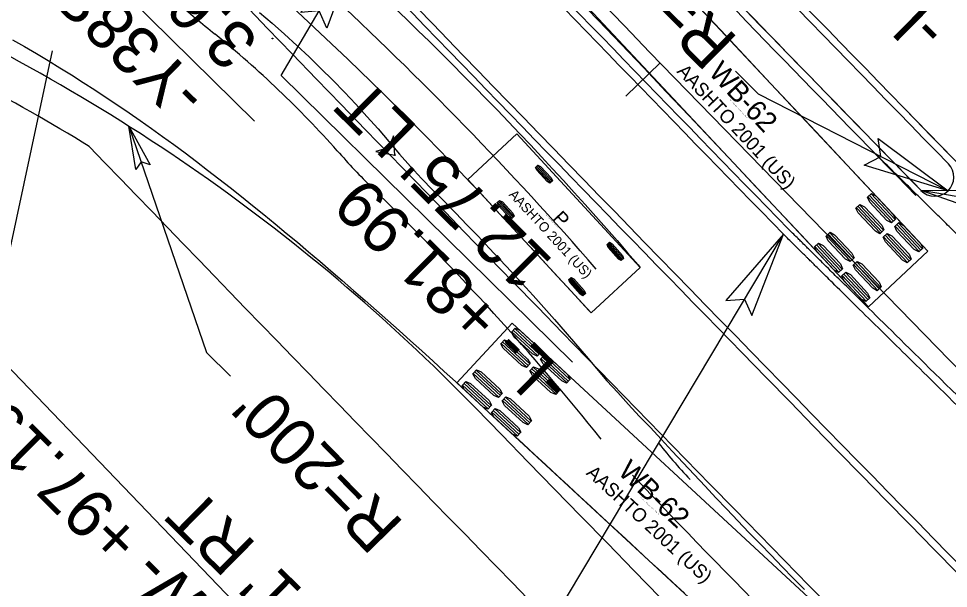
# Model space of a CAD drawing. Extents: x 1262642 to 1268358, y 767825 to 773481.
# Drawn here: x 1266795.4 to 1266892.6, y 772031 to 772090.6 of the extents above; entities that cross this region are included whole.
import ezdxf

# ---------------------------------------------------------------- set-up
doc = ezdxf.new("R2010")
doc.units = 0
for name, color, linetype in [('Prop Conc 1ft 6in Curb and Gutter', 7, 'Continuous'), ('Prop Conc 5in Monolithic Keyed In Island', 7, 'Continuous'), ('Prop Dimension', 7, 'Continuous'), ('Prop Dimension Text', 7, 'Continuous'), ('Prop EOT', 7, 'Continuous'), ('Prop Horizontal Alignment', 7, 'Continuous'), ('Prop Horizontal Alignment Tick Small', 7, 'Continuous'), ('Prop Lane Lines', 7, 'Continuous'), ('Prop Paved Shoulder', 7, 'Continuous'), ('Prop Shade Light', 7, 'Continuous'), ('Prop Shade Medium', 7, 'Continuous'), ('Prop Terminator CELL', 7, 'Continuous'), ('Scratch_Level_3', 7, 'Continuous')]:
    doc.layers.add(name, color=color, linetype=linetype)

msp = doc.modelspace()

# ---------------------------------------------------------------- linework, layer by layer
at = {"layer": 'Prop Conc 1ft 6in Curb and Gutter'}
msp.add_arc((1275047.307, 780021.225), 11414.25, 223.9578669, 225.4193188, dxfattribs=at)
msp.add_open_spline([(1266926.159, 772018.122), (1266925.893, 772018.382), (1266925.627, 772018.641), (1266925.229, 772019.03), (1266925.096, 772019.16), (1266924.897, 772019.354), (1266924.831, 772019.419), (1266924.698, 772019.549), (1266924.632, 772019.613), (1266924.034, 772020.197), (1266923.503, 772020.716), (1266921.91, 772022.273), (1266920.848, 772023.311), (1266917.663, 772026.425), (1266911.295, 772032.657), (1266900.694, 772043.056), (1266892.226, 772051.388), (1266885.88, 772057.643), (1266883.766, 772059.728), (1266880.595, 772062.858), (1266879.539, 772063.901), (1266878.35, 772065.075), (1266878.218, 772065.206), (1266878.02, 772065.401), (1266877.954, 772065.467), (1266877.822, 772065.597), (1266877.756, 772065.663), (1266877.425, 772065.989), (1266877.161, 772066.25), (1266876.633, 772066.771), (1266876.37, 772067.032), (1266875.842, 772067.554), (1266875.578, 772067.814), (1266875.315, 772068.075)], degree=3, dxfattribs=at)
at = {"layer": 'Prop Conc 5in Monolithic Keyed In Island'}
for centre, radius, start, end in [((1275047.307, 780021.225), 11385.75, 223.6505027, 224.2564693), ((1275047.307, 780021.225), 11389.75, 223.8019285, 224.2564698), ((1275047.307, 780021.225), 11389.75, 223.87202, 224.2564698), ((1275047.307, 780021.225), 11403.25, 223.9579874, 224.2224607), ((1266891.136, 772074.041), 2, 314.25374, 44.25374), ((1266891.136, 772074.041), 2, 224.25374, 314.25374)]:
    msp.add_arc(centre, radius, start, end, dxfattribs=at)
at = {"layer": 'Prop Dimension'}
msp.add_line((1266806.891, 772079.366), (1266814.985, 772055.706), dxfattribs=at)
at = {"layer": 'Prop Dimension Text'}
for p, q in [((1266820.023, 772079.893), (1266772.475, 772126.743)), ((1266822.822, 772084.668), (1266853.266, 772054.672)), ((1266872.691, 772082.773), (1266870.307, 772085.122)), ((1266872.691, 772082.773), (1266892.54, 772072.599)), ((1266832.757, 772014.086), (1266791.444, 772057.149)), ((1266814.985, 772055.706), (1266817.513, 772053.215))]:
    msp.add_line(p, q, dxfattribs=at)
for points in [[(1266822.822, 772084.668), (1266830.753, 772098.262)], [(1266792.936, 772059.488), (1266798.897, 772087.243)], [(1266907.856, 772069.557), (1266889.705, 772072.645)], [(1266843.752, 772015.175), (1266875.312, 772068.074)]]:
    msp.add_lwpolyline(points, dxfattribs=at)
at = {"layer": 'Prop EOT'}
for centre, radius, start, end in [((1275047.307, 780021.225), 11385, 223.6505027, 224.2564693), ((1275047.307, 780021.225), 11349, 223.9768445, 225.4019123), ((1275047.307, 780021.225), 11390.5, 223.8019285, 224.2564693), ((1275047.307, 780021.225), 11402.5, 223.9578586, 224.2223874), ((1275047.307, 780021.225), 11415, 223.9578709, 224.2520264), ((1266699.67, 771910.536), 200, 44.17518, 66.65746), ((1275047.307, 780021.225), 11415, 224.2520264, 225.4043192), ((1275047.307, 780021.225), 11439, 224.1751818, 225.4433837)]:
    msp.add_arc(centre, radius, start, end, dxfattribs=at)
msp.add_open_spline([(1266926.683, 772018.659), (1266926.417, 772018.918), (1266926.019, 772019.308), (1266925.62, 772019.696), (1266925.421, 772019.891), (1266925.355, 772019.955), (1266925.222, 772020.085), (1266924.625, 772020.669), (1266922.965, 772022.29), (1266919.249, 772025.923), (1266911.82, 772033.193), (1266901.22, 772043.591), (1266890.635, 772054.006), (1266883.235, 772061.305), (1266879.933, 772064.565), (1266878.745, 772065.739), (1266878.547, 772065.935), (1266878.481, 772066), (1266878.349, 772066.131), (1266878.018, 772066.457), (1266877.688, 772066.783), (1266877.161, 772067.305), (1266876.897, 772067.566), (1266876.369, 772068.087), (1266876.106, 772068.348), (1266875.842, 772068.608)], degree=3, dxfattribs=at)
at = {"layer": 'Prop Horizontal Alignment'}
msp.add_arc((1275047.307, 780021.225), 11400, 222.9935866, 225.4043192, dxfattribs=at)
at = {"layer": 'Prop Horizontal Alignment Tick Small'}
msp.add_line((1266862.433, 772085.997), (1266858.844, 772082.516), dxfattribs=at)
at = {"layer": 'Prop Lane Lines'}
for radius, start, end in [(11427, 222.9935866, 225.3637298), (11373, 223.9768445, 224.2564693), (11385, 224.2212142, 225.4043192)]:
    msp.add_arc((1275047.307, 780021.225), radius, start, end, dxfattribs=at)
msp.add_spline([(1266935.066, 772027.245), (1266934.378, 772027.917), (1266933.689, 772028.589), (1266933.001, 772029.262), (1266932.313, 772029.934), (1266931.625, 772030.606), (1266930.937, 772031.279), (1266930.249, 772031.951), (1266929.561, 772032.624), (1266928.873, 772033.296), (1266928.185, 772033.969), (1266927.497, 772034.642), (1266926.809, 772035.315), (1266926.122, 772035.987), (1266925.434, 772036.66), (1266924.746, 772037.333), (1266924.059, 772038.006), (1266923.371, 772038.679), (1266922.684, 772039.353), (1266921.997, 772040.026), (1266921.309, 772040.699), (1266920.622, 772041.372), (1266919.935, 772042.046), (1266919.248, 772042.719), (1266918.561, 772043.393), (1266917.874, 772044.066), (1266917.187, 772044.74), (1266916.5, 772045.414), (1266915.813, 772046.087), (1266915.126, 772046.761), (1266914.439, 772047.435), (1266913.752, 772048.109), (1266913.066, 772048.783), (1266912.379, 772049.457), (1266911.693, 772050.131), (1266911.006, 772050.805), (1266910.32, 772051.479), (1266909.633, 772052.154), (1266908.947, 772052.828), (1266908.261, 772053.502), (1266907.575, 772054.177), (1266906.889, 772054.851), (1266906.202, 772055.526), (1266905.516, 772056.201), (1266904.83, 772056.875), (1266904.145, 772057.55), (1266903.459, 772058.225), (1266902.773, 772058.9), (1266902.087, 772059.575), (1266901.401, 772060.25), (1266900.716, 772060.925), (1266900.03, 772061.6), (1266899.345, 772062.275), (1266898.659, 772062.95), (1266897.974, 772063.625), (1266897.288, 772064.301), (1266896.603, 772064.976), (1266895.918, 772065.652), (1266895.233, 772066.327), (1266894.548, 772067.003), (1266893.862, 772067.678), (1266893.177, 772068.354), (1266892.492, 772069.03), (1266891.808, 772069.705), (1266891.123, 772070.381), (1266890.438, 772071.057), (1266889.753, 772071.733), (1266889.068, 772072.409), (1266888.384, 772073.085), (1266887.699, 772073.762), (1266887.015, 772074.438), (1266886.33, 772075.114), (1266885.646, 772075.79), (1266884.277, 772077.143)], degree=3, dxfattribs=at)
at = {"layer": 'Prop Paved Shoulder'}
for centre, radius, start, end in [((1275047.307, 780021.225), 11339, 223.9768889, 225.4019123), ((1266699.67, 771910.536), 196, 58.26969, 66.65746), ((1275047.307, 780021.225), 11449, 223.9363178, 225.4433837)]:
    msp.add_arc(centre, radius, start, end, dxfattribs=at)
at = {"layer": 'Prop Shade Light'}
for centre, radius, start, end in [((1275047.307, 780021.225), 11339, 223.9768889, 225.401893), ((1275047.307, 780021.225), 11349, 223.9768445, 225.4019123), ((1266699.67, 771910.536), 200, 44.17518, 66.65746), ((1266699.67, 771910.536), 196, 58.26969, 66.65746), ((1275047.307, 780021.225), 11449, 223.9363178, 225.4433667), ((1275047.307, 780021.225), 11439, 224.1751818, 225.4433837)]:
    msp.add_arc(centre, radius, start, end, dxfattribs=at)
at = {"layer": 'Prop Shade Medium'}
for centre, radius, start, end in [((1275047.307, 780021.225), 11385.75, 223.6505027, 224.2564693), ((1275047.307, 780021.225), 11389.75, 223.8019285, 224.2564698), ((1266891.136, 772074.041), 2, 314.25374, 44.25374), ((1266891.136, 772074.041), 2, 224.25374, 314.25374)]:
    msp.add_arc(centre, radius, start, end, dxfattribs=at)
at = {"layer": 'Prop Terminator CELL'}
for points in [[(1266824.879, 772091.27), (1266830.753, 772098.262), (1266827.574, 772089.639), (1266826.772, 772091.439)], [(1266807.614, 772074.858), (1266806.891, 772079.366), (1266809.112, 772075.344), (1266808.169, 772075.629)], [(1266885.238, 772078.084), (1266892.54, 772072.599), (1266883.756, 772075.304), (1266885.51, 772076.203)], [(1266898.317, 772069.608), (1266889.705, 772072.645), (1266898.895, 772072.705), (1266897.493, 772071.32)], [(1266872.032, 772059.55), (1266875.312, 772068.074), (1266869.302, 772061.121), (1266871.265, 772061.289)]]:
    msp.add_lwpolyline(points, close=True, dxfattribs=at)
at = {"layer": 'Scratch_Level_3'}
for p, q in [((1266890.408, 772066.295), (1266857.609, 772101.342)), ((1266851.403, 772095.533), (1266884.201, 772060.487)), ((1266847.461, 772078.561), (1266842.318, 772073.812)), ((1266860.349, 772064.6), (1266847.461, 772078.561)), ((1266850.938, 772073.435), (1266849.412, 772075.088)), ((1266851.042, 772073.53), (1266849.516, 772075.184)), ((1266851.145, 772073.626), (1266849.619, 772075.279)), ((1266842.318, 772073.812), (1266855.206, 772059.852)), ((1266884.154, 772071.971), (1266886.66, 772069.294)), ((1266884.322, 772072.127), (1266886.827, 772069.45)), ((1266884.489, 772072.284), (1266886.995, 772069.607)), ((1266846.943, 772069.747), (1266845.417, 772071.4)), ((1266847.047, 772069.842), (1266845.52, 772071.495)), ((1266847.15, 772069.937), (1266845.624, 772071.591)), ((1266882.95, 772070.843), (1266885.455, 772068.166)), ((1266883.117, 772071), (1266885.623, 772068.323)), ((1266883.284, 772071.157), (1266885.79, 772068.479)), ((1266887.002, 772068.929), (1266889.507, 772066.251)), ((1266887.169, 772069.085), (1266889.674, 772066.408)), ((1266887.336, 772069.242), (1266889.842, 772066.565)), ((1266879.822, 772067.917), (1266882.328, 772065.239)), ((1266879.99, 772068.073), (1266882.495, 772065.396)), ((1266880.157, 772068.23), (1266882.662, 772065.553)), ((1266885.964, 772067.958), (1266888.47, 772065.281)), ((1266886.131, 772068.114), (1266888.637, 772065.437)), ((1266858.378, 772065.327), (1266856.902, 772067.025)), ((1266858.484, 772065.42), (1266857.008, 772067.117)), ((1266858.59, 772065.512), (1266857.114, 772067.21)), ((1266878.785, 772066.946), (1266881.29, 772064.269)), ((1266878.952, 772067.102), (1266881.458, 772064.425)), ((1266885.797, 772067.801), (1266888.302, 772065.124)), ((1266878.618, 772066.789), (1266881.123, 772064.112)), ((1266884.201, 772060.487), (1266890.408, 772066.295)), ((1266882.837, 772065.031), (1266885.342, 772062.354)), ((1266883.004, 772065.188), (1266885.51, 772062.51)), ((1266855.206, 772059.852), (1266860.349, 772064.6)), ((1266860.349, 772064.6), (1266860.349, 772064.6)), ((1266881.799, 772064.06), (1266884.305, 772061.383)), ((1266882.669, 772064.874), (1266885.175, 772062.197)), ((1266854.371, 772061.651), (1266852.895, 772063.35)), ((1266854.477, 772061.743), (1266853.002, 772063.442)), ((1266854.584, 772061.836), (1266853.108, 772063.534)), ((1266881.465, 772063.747), (1266883.97, 772061.07)), ((1266881.632, 772063.903), (1266884.138, 772061.226)), ((1266846.958, 772058.759), (1266841.185, 772052.521)), ((1266882.187, 772026.157), (1266846.958, 772058.759)), ((1266849.922, 772055.704), (1266847.231, 772058.195)), ((1266849.611, 772055.368), (1266846.92, 772057.859)), ((1266849.766, 772055.536), (1266847.075, 772058.027)), ((1266848.49, 772054.157), (1266845.799, 772056.648)), ((1266848.646, 772054.325), (1266845.955, 772056.816)), ((1266848.801, 772054.494), (1266846.11, 772056.984)), ((1266852.98, 772052.874), (1266850.289, 772055.365)), ((1266852.669, 772052.538), (1266849.978, 772055.029)), ((1266852.824, 772052.706), (1266850.133, 772055.197)), ((1266845.581, 772051.013), (1266842.89, 772053.504)), ((1266845.736, 772051.182), (1266843.045, 772053.672)), ((1266845.892, 772051.35), (1266843.201, 772053.84)), ((1266851.548, 772051.327), (1266848.857, 772053.818)), ((1266851.704, 772051.495), (1266849.013, 772053.986)), ((1266851.859, 772051.663), (1266849.168, 772054.154)), ((1266841.185, 772052.521), (1266876.414, 772019.918)), ((1266844.616, 772049.971), (1266841.924, 772052.461)), ((1266844.771, 772050.139), (1266842.08, 772052.629)), ((1266844.46, 772049.802), (1266841.769, 772052.293)), ((1266848.639, 772048.183), (1266845.948, 772050.674)), ((1266848.794, 772048.352), (1266846.103, 772050.842)), ((1266848.95, 772048.52), (1266846.259, 772051.01)), ((1266847.518, 772046.972), (1266844.827, 772049.463)), ((1266847.674, 772047.141), (1266844.983, 772049.631)), ((1266847.829, 772047.309), (1266845.138, 772049.799))]:
    msp.add_line(p, q, dxfattribs=at)
for points in [[(1266790.812, 772111.995), (1266792.752, 772111.527), (1266795.913, 772110.611), (1266798.935, 772109.551), (1266801.818, 772108.362), (1266804.617, 772107.004), (1266807.322, 772105.471), (1266809.924, 772103.769), (1266812.415, 772101.91), (1266814.776, 772099.976), (1266817.068, 772098.001), (1266819.34, 772096.002), (1266821.6, 772093.982), (1266823.906, 772091.884), (1266826.269, 772089.697), (1266828.666, 772087.44), (1266829.144, 772086.984)], [(1266884.201, 772060.487), (1266881.859, 772062.991), (1266879.516, 772065.494), (1266877.173, 772067.997), (1266874.829, 772070.499), (1266872.483, 772072.999), (1266870.135, 772075.498), (1266867.785, 772077.995), (1266865.432, 772080.488), (1266863.076, 772082.979), (1266860.716, 772085.466), (1266858.353, 772087.95), (1266855.985, 772090.429), (1266853.612, 772092.905)], [(1266812.324, 772091.98), (1266812.577, 772091.763), (1266812.83, 772091.546), (1266813.083, 772091.329), (1266813.337, 772091.113), (1266813.591, 772090.898), (1266813.846, 772090.683), (1266814.101, 772090.468), (1266814.357, 772090.254), (1266814.614, 772090.041), (1266814.87, 772089.829), (1266815.128, 772089.617), (1266815.386, 772089.406), (1266815.645, 772089.196), (1266815.904, 772088.987)], [(1266820.534, 772091.282), (1266821.854, 772090.145), (1266823.16, 772088.994), (1266824.448, 772087.824), (1266825.718, 772086.633), (1266826.97, 772085.422), (1266828.202, 772084.192), (1266829.415, 772082.943), (1266830.609, 772081.676), (1266831.782, 772080.389), (1266832.936, 772079.085), (1266834.069, 772077.763), (1266835.191, 772076.438), (1266836.33, 772075.145), (1266837.492, 772073.89), (1266838.679, 772072.677), (1266839.87, 772071.481), (1266841.054, 772070.278), (1266842.231, 772069.068), (1266843.401, 772067.85), (1266844.563, 772066.626), (1266845.718, 772065.395), (1266846.866, 772064.157), (1266848.006, 772062.912), (1266849.139, 772061.66), (1266850.265, 772060.402), (1266851.383, 772059.136), (1266852.493, 772057.865), (1266853.596, 772056.586), (1266854.691, 772055.302), (1266855.779, 772054.01), (1266856.873, 772052.731), (1266857.999, 772051.493), (1266859.126, 772050.26), (1266860.255, 772049.03), (1266861.414, 772047.839), (1266862.547, 772046.612), (1266863.696, 772045.377), (1266864.84, 772044.15), (1266865.98, 772042.932), (1266867.123, 772041.715), (1266868.268, 772040.502), (1266869.416, 772039.291), (1266870.565, 772038.083), (1266871.718, 772036.877), (1266872.872, 772035.674), (1266874.029, 772034.473), (1266875.187, 772033.275), (1266876.349, 772032.08), (1266877.512, 772030.886)], [(1266834.69, 772091.737), (1266835.903, 772090.57), (1266837.111, 772089.398), (1266838.313, 772088.22), (1266839.51, 772087.037), (1266840.702, 772085.849), (1266841.888, 772084.655), (1266843.07, 772083.456), (1266844.245, 772082.252), (1266845.416, 772081.043), (1266846.581, 772079.828), (1266847.74, 772078.608), (1266848.894, 772077.383), (1266850.043, 772076.153), (1266851.186, 772074.918), (1266852.324, 772073.678), (1266853.456, 772072.433), (1266854.582, 772071.182), (1266855.703, 772069.927), (1266856.818, 772068.667), (1266857.928, 772067.401), (1266859.032, 772066.131), (1266860.13, 772064.856), (1266860.349, 772064.6)], [(1266890.408, 772066.295), (1266888.065, 772068.799), (1266885.723, 772071.303), (1266883.38, 772073.806), (1266881.036, 772076.309), (1266878.694, 772078.812), (1266876.351, 772081.315), (1266874.008, 772083.818), (1266871.665, 772086.322), (1266869.323, 772088.825), (1266866.98, 772091.328)], [(1266794.72, 772088.423), (1266795.976, 772087.703), (1266797.221, 772086.974), (1266798.454, 772086.236), (1266799.679, 772085.489), (1266800.898, 772084.731), (1266802.112, 772083.96), (1266803.326, 772083.175), (1266804.525, 772082.385), (1266805.717, 772081.585), (1266806.902, 772080.776), (1266808.078, 772079.959), (1266809.253, 772079.129), (1266810.414, 772078.294), (1266811.581, 772077.442), (1266812.758, 772076.57), (1266813.942, 772075.68), (1266815.121, 772074.78), (1266816.298, 772073.871), (1266817.474, 772072.95), (1266818.65, 772072.018), (1266819.827, 772071.075), (1266821.003, 772070.122), (1266822.174, 772069.163), (1266823.343, 772068.196), (1266824.508, 772067.223), (1266825.671, 772066.244), (1266826.834, 772065.256), (1266828.009, 772064.249), (1266829.193, 772063.227), (1266830.385, 772062.19), (1266831.577, 772061.147), (1266832.766, 772060.098), (1266833.953, 772059.045), (1266835.139, 772057.987), (1266836.322, 772056.926), (1266837.503, 772055.86), (1266838.683, 772054.791), (1266839.861, 772053.718), (1266841.037, 772052.643), (1266842.213, 772051.564), (1266843.387, 772050.482), (1266844.559, 772049.398), (1266845.734, 772048.311), (1266846.913, 772047.22), (1266848.096, 772046.126), (1266849.279, 772045.03), (1266850.464, 772043.934), (1266851.65, 772042.836), (1266852.837, 772041.738), (1266854.025, 772040.638), (1266855.215, 772039.537), (1266856.413, 772038.428), (1266857.622, 772037.31), (1266858.841, 772036.181), (1266860.068, 772035.045), (1266861.296, 772033.909), (1266862.524, 772032.773), (1266863.752, 772031.636), (1266864.981, 772030.499)], [(1266829.144, 772086.984), (1266829.859, 772086.3), (1266831.048, 772085.155), (1266832.231, 772084.005), (1266833.41, 772082.849), (1266834.583, 772081.688), (1266835.751, 772080.522), (1266836.914, 772079.351), (1266838.071, 772078.175), (1266839.223, 772076.993), (1266840.37, 772075.806), (1266841.512, 772074.614), (1266842.648, 772073.417), (1266843.779, 772072.215), (1266844.905, 772071.008), (1266846.025, 772069.796), (1266847.145, 772068.584), (1266848.265, 772067.371), (1266849.384, 772066.158), (1266850.504, 772064.945), (1266851.623, 772063.733), (1266852.743, 772062.52), (1266853.863, 772061.307), (1266854.982, 772060.095), (1266855.206, 772059.852)], [(1266828.68, 772076.792), (1266828.901, 772076.543), (1266829.123, 772076.294), (1266829.346, 772076.046), (1266829.57, 772075.799), (1266829.794, 772075.553), (1266830.02, 772075.307), (1266830.246, 772075.062), (1266830.474, 772074.819), (1266830.702, 772074.576), (1266830.931, 772074.334), (1266831.161, 772074.093), (1266831.392, 772073.853), (1266831.625, 772073.614), (1266831.858, 772073.376), (1266832.093, 772073.139), (1266832.328, 772072.903), (1266832.565, 772072.668), (1266832.803, 772072.434), (1266833.042, 772072.202)], [(1266862.286, 772046.181), (1266862.495, 772045.921), (1266862.704, 772045.662), (1266862.916, 772045.404), (1266863.128, 772045.147), (1266863.342, 772044.892), (1266863.557, 772044.637), (1266863.774, 772044.384), (1266863.992, 772044.132), (1266864.212, 772043.881), (1266864.433, 772043.632), (1266864.655, 772043.384), (1266864.88, 772043.137), (1266865.105, 772042.892), (1266865.333, 772042.648), (1266865.561, 772042.405)]]:
    msp.add_lwpolyline(points, dxfattribs=at)
for points in [[(1266834.686, 772076.356), (1266834.543, 772078.351), (1266834.022, 772077.104), (1266832.722, 772076.734)], [(1266851.171, 772073.649), (1266850.913, 772073.411), (1266850.621, 772073.571), (1266849.523, 772074.761), (1266849.387, 772075.065), (1266849.644, 772075.303), (1266849.936, 772075.143), (1266851.035, 772073.953)], [(1266884.113, 772071.932), (1266884.531, 772072.323), (1266885.007, 772072.066), (1266886.811, 772070.138), (1266887.036, 772069.646), (1266886.618, 772069.255), (1266886.142, 772069.512), (1266884.338, 772071.439)], [(1266847.176, 772069.961), (1266846.918, 772069.723), (1266846.626, 772069.883), (1266845.527, 772071.073), (1266845.391, 772071.376), (1266845.649, 772071.614), (1266845.941, 772071.454), (1266847.04, 772070.264)], [(1266882.908, 772070.805), (1266883.326, 772071.195), (1266883.802, 772070.938), (1266885.606, 772069.011), (1266885.831, 772068.518), (1266885.414, 772068.127), (1266884.937, 772068.384), (1266883.133, 772070.312)], [(1266886.96, 772068.89), (1266887.378, 772069.281), (1266887.854, 772069.024), (1266889.658, 772067.096), (1266889.883, 772066.604), (1266889.466, 772066.213), (1266888.989, 772066.47), (1266887.185, 772068.397)], [(1266879.781, 772067.878), (1266880.198, 772068.269), (1266880.675, 772068.012), (1266882.479, 772066.084), (1266882.704, 772065.591), (1266882.286, 772065.201), (1266881.81, 772065.458), (1266880.006, 772067.385)], [(1266885.755, 772067.762), (1266886.173, 772068.153), (1266886.65, 772067.896), (1266888.453, 772065.969), (1266888.678, 772065.476), (1266888.261, 772065.085), (1266887.784, 772065.342), (1266885.98, 772067.27)], [(1266858.617, 772065.535), (1266858.352, 772065.304), (1266858.065, 772065.473), (1266857.002, 772066.695), (1266856.875, 772067.002), (1266857.14, 772067.233), (1266857.427, 772067.064), (1266858.49, 772065.842)], [(1266878.576, 772066.75), (1266878.994, 772067.141), (1266879.47, 772066.884), (1266881.274, 772064.957), (1266881.499, 772064.464), (1266881.082, 772064.073), (1266880.605, 772064.33), (1266878.801, 772066.258)], [(1266882.628, 772064.836), (1266883.046, 772065.226), (1266883.522, 772064.969), (1266885.326, 772063.042), (1266885.551, 772062.549), (1266885.133, 772062.158), (1266884.657, 772062.415), (1266882.853, 772064.343)], [(1266881.423, 772063.708), (1266881.841, 772064.099), (1266882.317, 772063.842), (1266884.121, 772061.914), (1266884.346, 772061.422), (1266883.929, 772061.031), (1266883.452, 772061.288), (1266881.648, 772063.215)], [(1266854.61, 772061.859), (1266854.345, 772061.628), (1266854.058, 772061.797), (1266852.996, 772063.02), (1266852.869, 772063.327), (1266853.134, 772063.557), (1266853.421, 772063.388), (1266854.483, 772062.166)], [(1266849.961, 772055.746), (1266849.572, 772055.326), (1266849.078, 772055.549), (1266847.141, 772057.342), (1266846.881, 772057.817), (1266847.269, 772058.237), (1266847.763, 772058.014), (1266849.701, 772056.221)], [(1266848.84, 772054.535), (1266848.451, 772054.115), (1266847.958, 772054.338), (1266846.02, 772056.131), (1266845.76, 772056.606), (1266846.149, 772057.026), (1266846.643, 772056.804), (1266848.58, 772055.01)], [(1266853.019, 772052.916), (1266852.63, 772052.496), (1266852.136, 772052.719), (1266850.199, 772054.512), (1266849.939, 772054.987), (1266850.328, 772055.407), (1266850.821, 772055.184), (1266852.759, 772053.391)], [(1266845.931, 772051.392), (1266845.542, 772050.972), (1266845.048, 772051.194), (1266843.111, 772052.987), (1266842.851, 772053.462), (1266843.239, 772053.882), (1266843.733, 772053.66), (1266845.671, 772051.867)], [(1266851.898, 772051.705), (1266851.509, 772051.285), (1266851.016, 772051.508), (1266849.078, 772053.301), (1266848.818, 772053.776), (1266849.207, 772054.196), (1266849.701, 772053.973), (1266851.638, 772052.18)], [(1266844.81, 772050.181), (1266844.421, 772049.761), (1266843.928, 772049.983), (1266841.99, 772051.776), (1266841.73, 772052.251), (1266842.119, 772052.671), (1266842.613, 772052.449), (1266844.55, 772050.656)], [(1266848.989, 772048.561), (1266848.6, 772048.142), (1266848.106, 772048.364), (1266846.169, 772050.157), (1266845.909, 772050.632), (1266846.298, 772051.052), (1266846.791, 772050.83), (1266848.729, 772049.037)], [(1266847.868, 772047.35), (1266847.479, 772046.931), (1266846.986, 772047.153), (1266845.048, 772048.946), (1266844.788, 772049.421), (1266845.177, 772049.841), (1266845.671, 772049.619), (1266847.608, 772047.826)]]:
    msp.add_lwpolyline(points, close=True, dxfattribs=at)
for centre in [(1266821.91, 772088.551), (1266821.91, 772088.551), (1266834.686, 772076.356), (1266834.686, 772076.356)]:
    msp.add_circle(centre, 0.0417, dxfattribs=at)
for centre, radius, start, end in [((1266573.771, 771819.313), 373.618, 41.00041, 47.23753), ((1266748.551, 772005.634), 107.164, 41.60668, 51.06034), ((1266638.396, 771872.057), 279.187, 38.70035, 45.79804), ((1267582.953, 772728.752), 996.884, 223.476297, 226.032311)]:
    msp.add_arc(centre, radius, start, end, dxfattribs=at)

# ---------------------------------------------------------------- texts
at = {"layer": 'Prop Dimension'}
msp.add_text("R=200'", height=5, rotation=134.2575, dxfattribs=at).set_placement((1266835.769, 772037.804))
at = {"layer": 'Prop Dimension Text'}
for s, p in [('-Y38SW- +95.38', (1266815.384, 772083.074)), ('-L- +30.82', (1266892.738, 772089.886)), ("3.65' RT", (1266820.648, 772088.416)), ("R=2.00'", (1266870.711, 772088.498)), ("12.75' LT", (1266851.386, 772065.252)), ('-L- +81.99', (1266853.355, 772052.783)), ('-Y38SW- +97.19', (1266829.246, 772016.274)), ("12.51' RT", (1266834.51, 772021.617))]:
    msp.add_text(s, height=5, rotation=135.42387, dxfattribs=at).set_placement(p)
at = {"layer": 'Scratch_Level_3'}
for s, height, rotation, p in [('WB-62', 2.125, 313.10268, (1266867.399, 772084.909)), ('AASHTO 2001 (US)', 1.41667, 313.10268, (1266864.111, 772085.054)), ('(c) 2016 Transoft Solutions, Inc. All rights reserved.', 0.085, 313.10268, (1266869.69, 772082.15)), ('AASHTO 2001 (US)', 1, 312.71378, (1266846.557, 772072.161)), ('(c) 2016 Transoft Solutions, Inc. All rights reserved.', 0.06, 312.71378, (1266850.482, 772070.085)), ('P', 1.5, 312.71378, (1266851.083, 772069.655)), ('WB-62', 2.125, 317.21729, (1266857.903, 772043.072)), ('AASHTO 2001 (US)', 1.41667, 317.21729, (1266854.612, 772042.98)), ('(c) 2016 Transoft Solutions, Inc. All rights reserved.', 0.085, 317.21729, (1266860.386, 772040.484))]:
    msp.add_text(s, height=height, rotation=rotation, dxfattribs=at).set_placement(p)

doc.saveas('drawing.dxf')
